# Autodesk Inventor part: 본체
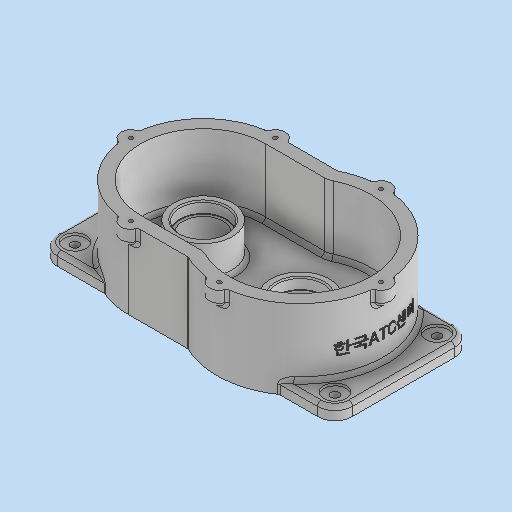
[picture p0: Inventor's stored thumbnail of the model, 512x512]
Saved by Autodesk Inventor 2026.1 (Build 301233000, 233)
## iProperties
Created: 2025-11
Part Number: 본체
Material: 일반
Document SubType Name: Modeling
Designer: PC-30
Density: 1 g/cm^3
Appearance: 기본값
Author: PC-30
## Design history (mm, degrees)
sketch "스케치1"
  geometry: L1 (-42.5, 60)-(5.684, 60); L2 (35.5, 67)-(35.5, -67); L3 (5.684, -60)-(-42.5, -60); L4 (-42.5, -60)-(-42.5, 60); L5 (-102.5, 0)-(102.5, 0); A1 r 60 centre (-42.5, 0) between (-42.5, 60) and (-42.5, -60); A2 r 67 centre (35.5, 0) between (5.684, -60) and (5.684, 60); 3 further points
  constraints: 10 end point, 8 point on circle, 4 midpoint, 2 centre point, 2 parallel, 1 coincident, 1 horizontal, 1 perpendicular, 1 tangent, 1 vertical alignment
  dimensions: "d0" = 60 radius of A1; "d1" = 67 radius of A2; "d2" = 78 distance of point (35.5, 0) A1.centre
extrude "돌출1" new body sketch "스케치1" distance "d3" = 64; taper "d4" = 0 deg
sketch "스케치2"
  geometry: L1 (5.684, 60)-(-42.5, 60) reference; L2 (-42.5, -60)-(5.684, -60) reference; L3 (-42.5, 50)-(8.132, 50); L4 (8.132, -50)-(-42.5, -50); A1 r 60 centre (-42.5, 0) between (-42.5, 60) and (-42.5, -60) reference; A2 r 67 centre (35.5, 0) between (5.684, -60) and (5.684, 60) reference; A3 r 57 centre (35.5, 0) between (8.132, -50) and (8.132, 50); A4 r 50 centre (-42.5, 0) between (-42.5, 50) and (-42.5, -50); 1 further point
  constraints: 4 end point, 4 point on circle, 2 centre point, 3 other
  dimensions: "d5" = 10 distance between parallel lines of L1 L3
extrude "돌출2" cut sketch "스케치2" distance "d6" = 54; taper "d7" = 0 deg
sketch "스케치3"
  geometry: L1 (118.5, 55)-(118.5, -55); L2 (-118.5, -55)-(-118.5, 55); L3 (5.684, 60)-(-42.5, 60) reference; L4 (-42.5, -60)-(5.684, -60) reference; L5 (-118.5, 55)-(-66.479, 55); L6 (73.762, 55)-(118.5, 55); L7 (118.5, -55)-(73.762, -55); L8 (-66.479, -55)-(-118.5, -55); A1 r 67 centre (35.5, 0) between (5.684, -60) and (5.684, 60) reference; A2 r 60 centre (-42.5, 0) between (-42.5, 60) and (-42.5, -60) reference; 2 further points
  constraints: 12 end point, 5 parallel, 4 point on circle, 2 horizontal, 2 perpendicular, 1 horizontal alignment, 1 midpoint
  dimensions: "d9" = 237 distance between parallel lines of L1 L2; "d10" = 154 distance from line of A1.centre L2; "d11" = 110 distance between parallel lines of L8 L5; "d12" = 110 distance between parallel lines of L7 L6; "d13" = 55 distance from line of L6 A1.centre
extrude "돌출3" join sketch "스케치3" distance "d14" = 10; taper "d15" = 0 deg
node "작업 평면1"
sketch "스케치4"
  geometry: A1 r 8 centre (-100.5, 0) between (-101.983, 7.861) and (-101.983, -7.861); A2 r 50 centre (-42.5, 0) between (-42.5, 50) and (-42.5, -50) reference; A3 r 60 centre (-42.5, 0) between (-42.5, 60) and (-42.5, -60) reference; 1 further point
  constraints: 4 point on circle, 1 centre point, 1 horizontal alignment
  dimensions: "d17" = 58 distance of A2.centre A1.centre; "d18" = 16 diameter of A1
extrude "돌출4" join sketch "스케치4" distance "d19" = 12; taper "d20" = 0 deg
sketch "스케치5"
  geometry: A1 r 8 centre (-100.5, 0) between (-101.983, 7.861) and (-101.983, -7.861) reference; 2 further points
  constraints: 1 coincident
hole "구멍1" sketch "스케치5" at (-100.5, 0) diameter "d21" = 3.242; stored, may be unused: countersink angle "d25" = 90 deg, drill point angle "d27" = 118 deg; dims "d22" = 8, "d23" = 37, "d24" = 9, "d26" = 10
sketch "스케치6"
  geometry: A1 r 67 centre (35.5, 0) between (5.684, -60) and (5.684, 60) reference; A2 r 57 centre (35.5, 0) between (8.132, -50) and (8.132, 50) reference; A3 r 8 centre (100.5, 0) between (102.038, -7.851) and (102.038, 7.851); 1 further point
  constraints: 4 point on circle, 1 centre point, 1 horizontal alignment
  dimensions: "d31" = 65 distance of A1.centre A3.centre; "d32" = 16 diameter of A3
extrude "돌출5" join sketch "스케치6" distance "d33" = 12; taper "d34" = 0 deg
sketch "스케치7"
  geometry: A1 r 8 centre (100.5, 0) between (102.038, -7.851) and (102.038, 7.851) reference; 2 further points
  constraints: 1 coincident
hole "구멍2" sketch "스케치7" at (100.5, 0) diameter "d35" = 3.242; stored, may be unused: countersink angle "d39" = 90 deg, drill point angle "d41" = 118 deg; dims "d36" = 8, "d37" = 4, "d38" = 2, "d40" = 10
sketch "스케치8"
  geometry: C1 r 23.5 at (-42.5, 0); A1 r 50 centre (-42.5, 0) between (-42.5, 50) and (-42.5, -50) reference; 1 further point
  constraints: 1 centre point, 1 concentric
  dimensions: "d45" = 47 diameter of C1
extrude "돌출6" join sketch "스케치8" distance "d46" = 26; taper "d47" = 0 deg
sketch "스케치9"
  geometry: C1 r 23.5 at (35.5, 0); A1 r 57 centre (35.5, 0) between (8.132, -50) and (8.132, 50) reference; 1 further point
  constraints: 1 centre point, 1 concentric
  dimensions: "d48" = 47 diameter of C1
extrude "돌출7" join sketch "스케치9" distance "d49" = 12; taper "d50" = 0 deg
sketch "스케치10"
  geometry: C1 r 23.5 at (0, 0) reference; 2 further points
  constraints: 1 coincident
hole "구멍3" sketch "스케치10" at (0, 0) diameter "d51" = 32; stored, may be unused: countersink angle "d55" = 90 deg, drill point angle "d57" = 0 deg; dims "d52" = 8, "d53" = 37, "d54" = 9, "d56" = 25
sketch "스케치11"
  geometry: C1 r 16 at (0, 0) reference; 2 further points
  constraints: 1 coincident
hole "구멍4" sketch "스케치11" at (0, 0) diameter "d58" = 28; stored, may be unused: countersink angle "d62" = 90 deg, drill point angle "d64" = 0 deg; dims "d59" = 6, "d60" = 37, "d61" = 9, "d63" = 3
sketch "스케치12"
  geometry: C1 r 23.5 at (0, 0) reference; 2 further points
  constraints: 1 coincident
hole "구멍5" sketch "스케치12" at (0, 0) diameter "d65" = 30; stored, may be unused: countersink angle "d69" = 90 deg, drill point angle "d71" = 0 deg; dims "d66" = 6, "d67" = 37, "d68" = 9, "d70" = 13.7
sketch "스케치13"
  geometry: C1 r 15 at (0, 0) reference; 2 further points
  constraints: 1 coincident
hole "구멍6" sketch "스케치13" at (0, 0) diameter "d72" = 35; stored, may be unused: countersink angle "d76" = 90 deg, drill point angle "d78" = 0 deg; dims "d73" = 6, "d74" = 37, "d75" = 9, "d77" = 8.3
chamfer "모따기1" distance "d79" = 1; stored, may be unused: second distance "d80" = 2, angle "d81" = 45 deg
chamfer "모따기2" distance "d82" = 0.8; stored, may be unused: second distance "d83" = 2, angle "d84" = 30 deg
chamfer "모따기3" distance "d85" = 1; stored, may be unused: second distance "d86" = 2, angle "d87" = 45 deg
chamfer "모따기4" distance "d88" = 1; stored, may be unused: second distance "d89" = 2, angle "d90" = 45 deg
fillet "모깎기1" dims "d91" = 0.3
fillet "모깎기2" dims "d92" = 0.3
fillet "모깎기3" dims "d93" = 0.3
fillet "모깎기4" dims "d94" = 13
fillet "모깎기5" dims "d95" = 3
fillet "모깎기6" dims "d96" = 3
fillet "모깎기7" dims "d97" = 3
fillet "모깎기8" dims "d98" = 14
sketch "스케치14"
  geometry: A1 r 14 centre (104.5, -41) between (104.5, -55) and (118.5, -41) reference; A2 r 14 centre (104.5, 41) between (118.5, 41) and (104.5, 55) reference; A3 r 14 centre (-104.5, 41) between (-104.5, 55) and (-118.5, 41) reference; A4 r 14 centre (-104.5, -41) between (-118.5, -41) and (-104.5, -55) reference; 5 further points
  constraints: 4 coincident
hole "구멍7" sketch "스케치14" at (104.5, -41), (104.5, 41), (-104.5, 41), (-104.5, -41) diameter "d99" = 6.6; stored, may be unused: countersink angle "d103" = 90 deg, drill point angle "d105" = 0 deg; dims "d100" = 6, "d101" = 18, "d102" = 2, "d104" = 8.3
fillet "모깎기9" dims "d106" = 3
fillet "모깎기10" dims "d107" = 3
fillet "모깎기11" dims "d108" = 3
node "작업 평면2"
sketch "스케치15"
  geometry: L1 (-33.183, 35.422)-(33.183, 35.422); L2 (33.183, 35.422)-(33.183, 24.578); L3 (33.183, 24.578)-(-33.183, 24.578); L4 (-33.183, 24.578)-(-33.183, 35.422); L5 (41, 0)-(-41, 0) reference; L6 (-33.183, 30)-(33.183, 30); 3 further points
  constraints: 4 midpoint, 2 end point, 1 vertical alignment, 2 other
  dimensions: "d110" = 30 distance between parallel lines of L5 L6
feature "엠보싱1" sketch "스케치15" dims "d5" = 10, "d111" = 0.5, "d112" = 0
fillet "모깎기12" dims "d113" = 3
node "솔리드1"
pattern_circular "원형 패턴1" dims "d29" = 180 deg
pattern_circular "원형 패턴2" dims "d43" = 180 deg
node "투영된 루프1"
node "투영된 루프2"
feature "A9D066F2-1C7D-4E18-AEED-F7BC21143FA4" dims "d51" = 32, "d52" = 8, "d53" = 37, "d54" = 9, "d55" = 90 deg, "d56" = 25, "d57" = 0
other parameters: "d16" = 0
